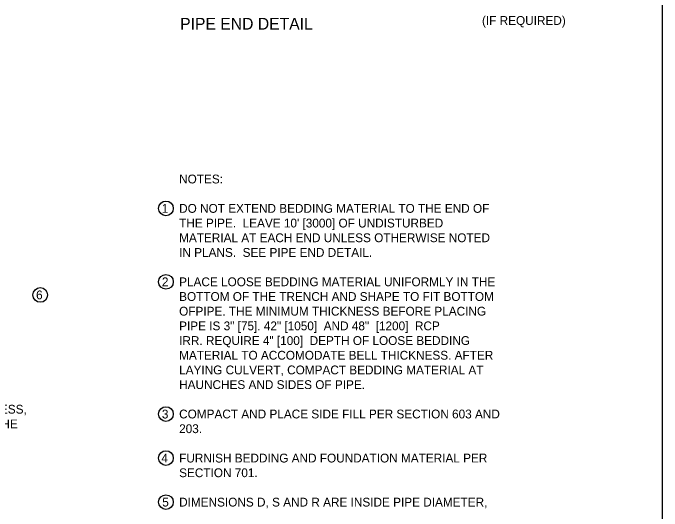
# Model space of a CAD drawing. Extents: x 49991.4 to 50021, y 49987.6 to 50011.4.
# Drawn here: x 50012.329 to 50016.75, y 49992.398 to 49995.789 of the extents above; entities that cross this region are included whole.
import ezdxf

# ---------------------------------------------------------------- set-up
doc = ezdxf.new("R2010")
doc.units = 0
doc.layers.add('Level 1', color=7, linetype='Continuous')
doc.layers.add('Level 2', color=7, linetype='Continuous')

msp = doc.modelspace()

# ---------------------------------------------------------------- linework, layer by layer
at = {"layer": 'Level 1'}
msp.add_lwpolyline([(49999.3835, 49998.9992), (50016.7501, 49998.9992), (50016.7501, 49987.7988), (49999.3835, 49987.7988)], close=True, dxfattribs=at)
at = {"layer": 'Level 2'}
for centre in [(50013.3708, 49994.4587), (50013.3708, 49993.9587), (50012.5145, 49993.8695), (50013.3708, 49993.0583), (50013.3708, 49992.7587), (50013.3708, 49992.4587)]:
    msp.add_circle(centre, 0.05, dxfattribs=at)

# ---------------------------------------------------------------- texts
for s, height, p in [('PIPE END DETAIL', 0.08, (50013.4675, 49995.676)), ('(IF REQUIRED)', 0.06, (50015.5238, 49995.7079)), ('NOTES:', 0.06, (50013.4608, 49994.6287)), ('1', 0.06, (50013.3423, 49994.4287)), ('DO NOT EXTEND BEDDING MATERIAL TO THE END OF', 0.06, (50013.4608, 49994.4287)), ("THE PIPE.  LEAVE 10' [3000] OF UNDISTURBED ", 0.06, (50013.4608, 49994.3287)), ('MATERIAL AT EACH END UNLESS OTHERWISE NOTED', 0.06, (50013.4608, 49994.2287)), ('IN PLANS.  SEE PIPE END DETAIL.', 0.06, (50013.4608, 49994.1287)), ('2', 0.06, (50013.3433, 49993.9287)), ('PLACE LOOSE BEDDING MATERIAL UNIFORMLY IN THE', 0.06, (50013.4608, 49993.9287)), ('BOTTOM OF THE TRENCH AND SHAPE TO FIT BOTTOM ', 0.06, (50013.4608, 49993.8287)), ('OFPIPE. THE MINIMUM THICKNESS BEFORE PLACING ', 0.06, (50013.4608, 49993.7287)), ('PIPE IS 3" [75]. 42" [1050]  AND 48"  [1200]  RCP ', 0.06, (50013.4608, 49993.6287)), ('IRR. REQUIRE 4" [100]  DEPTH OF LOOSE BEDDING ', 0.06, (50013.4608, 49993.5287)), ('MATERIAL TO ACCOMODATE BELL THICKNESS. AFTER ', 0.06, (50013.4608, 49993.4287)), ('LAYING CULVERT, COMPACT BEDDING MATERIAL AT ', 0.06, (50013.4608, 49993.3287)), ('HAUNCHES AND SIDES OF PIPE.', 0.06, (50013.4608, 49993.2287)), ('1\'-0" [300] MIN. THICKNESS,', 0.06, (50011.3672, 49993.0613)), ('3', 0.06, (50013.3432, 49993.0283)), ('COMPACT AND PLACE SIDE FILL PER SECTION 603 AND ', 0.06, (50013.4608, 49993.0287)), ('OR AS DIRECTED BY THE', 0.06, (50011.3672, 49992.9613)), ('203.', 0.06, (50013.4608, 49992.9287)), ('4', 0.06, (50013.3397, 49992.7287)), ('FURNISH BEDDING AND FOUNDATION MATERIAL PER', 0.06, (50013.4608, 49992.7287)), ('SECTION 701.', 0.06, (50013.4608, 49992.6287)), ('5', 0.06, (50013.3459, 49992.4287)), ('DIMENSIONS D, S AND R ARE INSIDE PIPE DIAMETER, ', 0.06, (50013.4608, 49992.4287))]:
    msp.add_text(s, height=height, dxfattribs=at).set_placement(p)
msp.add_text('6', height=0.06, rotation=360, dxfattribs=at).set_placement((50012.4863, 49993.8395))

doc.saveas('drawing.dxf')
